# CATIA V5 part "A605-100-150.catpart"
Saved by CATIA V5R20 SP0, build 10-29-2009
Part number: A605-100-150
Source: Unknown
Property "A": "70.000"
Property "ARTICLENO": "A605-100-150"
Property "BOMINFO": "A605-100-150"
Property "CODE": "A605-100-150"
Property "D": "9.000"
Property "FORM": "D"
Property "L": "150.000"
Property "L1": "60.000"
Property "LINA": "A605-100-150"
Property "NB": "A605-100-150"
Property "NBSYN": "$CODE."
Property "NN": "A605"
Property "NT": "Wear Plates, self-lubricating"
Property "SCREW": "6*M8X16"
Property "SUPPLIER": "CF"
Property "W": "100.000"
Bounding box of the stored display mesh (mm): x -100 to 0, y 0 to 5, z -150 to 0
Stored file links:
  C:\Users\Utente\Desktop\3D files A605\A605-100-150.catpart
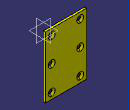
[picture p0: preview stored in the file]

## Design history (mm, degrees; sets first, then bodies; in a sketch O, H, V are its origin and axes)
Body1 "Geometry.1" (main body)
  Solid1 "A605-100-150.catpart": solid without history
